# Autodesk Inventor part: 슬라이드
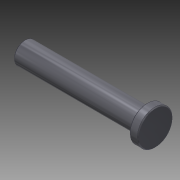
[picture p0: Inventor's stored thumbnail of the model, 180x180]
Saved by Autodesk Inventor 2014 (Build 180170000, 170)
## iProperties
Created: 2015-10
Part Number: 슬라이드
Document SubType Name: Modeling
Designer: mdu
Density: 1 g/cm^3
Material: 강철, 연강
Appearance: 진회색
Author: mdu
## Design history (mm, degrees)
sketch "스케치1"
  geometry: L1 (-75, 162)-(-75, 58) reference; L2 (-128, 110)-(22, 110); L3 (-128, 110)-(-128, 122.5); L4 (-128, 122.5)-(12, 122.5); L5 (12, 122.5)-(12, 130); L6 (12, 130)-(22, 130); L7 (22, 130)-(22, 110); 2 further points
  constraints: 12 end point, 3 parallel, 3 perpendicular, 1 midpoint, 1 point on line
  dimensions: "d0" = 40 diameter of L6 L2; "d1" = 25 diameter of L4 L2; "d2" = 10 distance of L5.end L6.end; "d3" = 150 distance of L2.start L2.end; "d4" = 53 distance between parallel lines of L3 L1
revolve "회전1" sketch "스케치1" stored, may be unused: angle "d5" = 90 deg
hole "구멍1" diameter "d11" = 10.106; stored, may be unused: countersink angle "d15" = 90 deg, drill point angle "d17" = 118 deg; dims "d12" = 22, "d13" = 4, "d14" = 2, "d16" = 25, "d18" = 10, "d19" = 10
chamfer "모따기1" distance "d6" = 1; stored, may be unused: second distance "d7" = 2, angle "d8" = 45 deg
node "솔리드1"
node "참조1"
